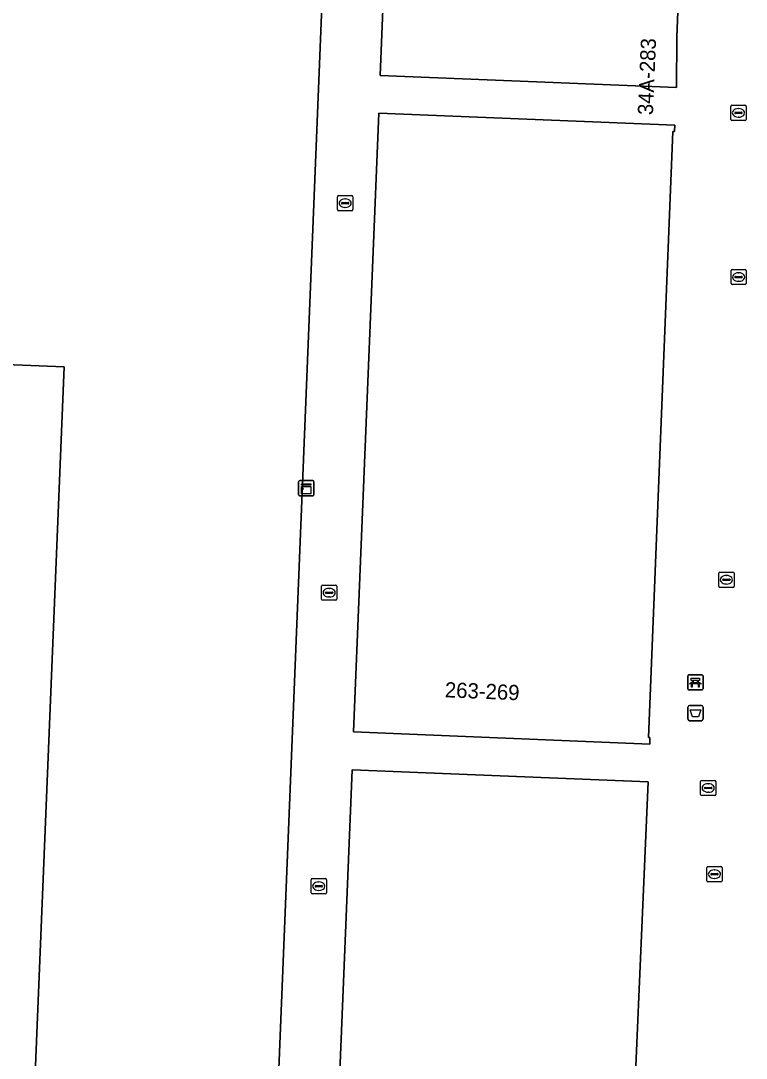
# Model space of a CAD drawing. Extents: x 160888 to 161385, y 386490 to 386908.
# Drawn here: x 161141.4 to 161189.1, y 386584.9 to 386653.1 of the extents above; entities that cross this region are included whole.
import ezdxf

# ---------------------------------------------------------------- set-up
doc = ezdxf.new("R2010")
doc.units = 0
for name, color, linetype in [('IMGEO_Afvalbak', 7, 'Continuous'), ('IMGEO_Bank', 7, 'Continuous'), ('IMGEO_Kast', 7, 'Continuous'), ('IMGEO_Kolk', 7, 'Continuous'), ('IMGEO_Pand', 7, 'Continuous'), ('IMGEO_Pand_nummerreeks', 7, 'Continuous'), ('IMGEO_Rioolput', 7, 'Continuous'), ('IMGEO_Voetgangersgebied_open', 7, 'Continuous')]:
    doc.layers.add(name, color=color, linetype=linetype)

msp = doc.modelspace()

# ---------------------------------------------------------------- linework, layer by layer
at = {"layer": 'IMGEO_Afvalbak'}
for p, q in [((161185.269, 386607.204), (161185.269, 386608.004)), ((161185.269, 386608.004), (161185.269, 386607.204)), ((161185.369, 386608.104), (161186.159, 386608.104)), ((161186.159, 386608.104), (161185.369, 386608.104)), ((161186.259, 386608.004), (161186.259, 386607.204)), ((161186.259, 386607.204), (161186.259, 386608.004)), ((161186.159, 386607.104), (161185.369, 386607.104)), ((161185.369, 386607.104), (161186.159, 386607.104))]:
    msp.add_line(p, q, dxfattribs=at)
msp.add_lwpolyline([(161185.412, 386607.818), (161186.116, 386607.818), (161185.967, 386607.348), (161185.561, 386607.348), (161185.412, 386607.818)], dxfattribs=at)
for centre, start, end in [((161185.369, 386608.004), 90, 180), ((161185.369, 386608.004), 90, 180), ((161186.159, 386608.004), 0, 90), ((161186.159, 386608.004), 360, 90), ((161185.369, 386607.204), 180, 270), ((161185.369, 386607.204), 180, 270), ((161186.159, 386607.204), 270, 0), ((161186.159, 386607.204), 270, 0)]:
    msp.add_arc(centre, 0.1, start, end, dxfattribs=at)
at = {"layer": 'IMGEO_Bank'}
for p, q in [((161185.256, 386609.198), (161185.256, 386610.039)), ((161185.256, 386610.039), (161185.256, 386609.198)), ((161185.331, 386610.123), (161186.172, 386610.123)), ((161186.172, 386610.123), (161185.331, 386610.123)), ((161186.256, 386610.048), (161186.256, 386609.207)), ((161186.256, 386609.207), (161186.256, 386610.048)), ((161185.953, 386609.521), (161185.56, 386609.521)), ((161185.565, 386609.629), (161185.565, 386609.735)), ((161185.609, 386609.735), (161185.609, 386609.629)), ((161185.897, 386609.741), (161185.615, 386609.741)), ((161185.615, 386609.623), (161185.897, 386609.623)), ((161185.903, 386609.629), (161185.903, 386609.735)), ((161185.947, 386609.735), (161185.947, 386609.629)), ((161186.181, 386609.123), (161185.34, 386609.123)), ((161185.34, 386609.123), (161186.181, 386609.123))]:
    msp.add_line(p, q, dxfattribs=at)
for points in [[(161185.559, 386609.741), (161185.473, 386609.741), (161185.473, 386609.902), (161186.036, 386609.902), (161186.036, 386609.741), (161185.953, 386609.741)], [(161185.503, 386609.521), (161185.361, 386609.521), (161185.473, 386609.623), (161185.559, 386609.623)], [(161185.553, 386609.514), (161185.553, 386609.307), (161185.51, 386609.307), (161185.51, 386609.514)], [(161185.953, 386609.623), (161186.036, 386609.623), (161186.148, 386609.521), (161186.009, 386609.521)], [(161186.003, 386609.514), (161186.003, 386609.307), (161185.959, 386609.307), (161185.959, 386609.514)]]:
    msp.add_lwpolyline(points, dxfattribs=at)
for centre, radius, start, end in [((161185.334, 386610.045), 0.0779, 92.4484, 184.28452), ((161185.334, 386610.045), 0.0779, 92.4484, 184.28452), ((161186.178, 386610.045), 0.0779, 2.4484, 94.28452), ((161186.178, 386610.045), 0.0779, 2.4484, 94.28452), ((161185.334, 386609.201), 0.0779, 182.4484, 274.28452), ((161185.334, 386609.201), 0.0779, 182.4484, 274.28452), ((161185.503, 386609.514), 0.00671, 2.89567, 87.10433), ((161185.56, 386609.514), 0.00671, 92.89567, 177.10433), ((161185.558, 386609.734), 0.00671, 2.89567, 87.10433), ((161185.558, 386609.63), 0.00671, 272.89567, 357.10433), ((161185.615, 386609.734), 0.00671, 92.89567, 177.10433), ((161185.615, 386609.63), 0.00671, 182.89567, 267.10433), ((161185.897, 386609.734), 0.00671, 2.89567, 87.10433), ((161185.897, 386609.63), 0.00671, 272.89567, 357.10433), ((161185.954, 386609.734), 0.00671, 92.89567, 177.10433), ((161185.954, 386609.63), 0.00671, 182.89567, 267.10433), ((161185.952, 386609.514), 0.00671, 2.89567, 87.10433), ((161186.009, 386609.514), 0.00671, 92.89567, 177.10433), ((161186.178, 386609.201), 0.0779, 272.4484, 4.28452), ((161186.178, 386609.201), 0.0779, 272.4484, 4.28452)]:
    msp.add_arc(centre, radius, start, end, dxfattribs=at)
at = {"layer": 'IMGEO_Kast'}
for p, q in [((161159.738, 386622.889), (161160.579, 386622.889)), ((161160.579, 386622.889), (161159.738, 386622.889)), ((161159.663, 386621.964), (161159.663, 386622.805)), ((161159.663, 386622.805), (161159.663, 386621.964)), ((161160.663, 386622.814), (161160.663, 386621.973)), ((161160.663, 386621.973), (161160.663, 386622.814)), ((161160.588, 386621.889), (161159.747, 386621.889)), ((161159.747, 386621.889), (161160.588, 386621.889))]:
    msp.add_line(p, q, dxfattribs=at)
for points in [[(161159.858, 386622.679), (161160.458, 386622.679), (161160.458, 386622.594), (161159.858, 386622.594), (161159.858, 386622.679)], [(161159.858, 386622.504), (161160.458, 386622.504), (161160.458, 386622.015), (161159.858, 386622.015), (161159.858, 386622.504)]]:
    msp.add_lwpolyline(points, dxfattribs=at)
msp.add_circle((161159.942, 386622.353), 0.0377, dxfattribs=at)
for centre, start, end in [((161159.741, 386622.811), 92.4484, 184.28452), ((161159.741, 386622.811), 92.4484, 184.28452), ((161160.585, 386622.811), 2.4484, 94.28452), ((161160.585, 386622.811), 2.4484, 94.28452), ((161159.741, 386621.967), 182.4484, 274.28452), ((161159.741, 386621.967), 182.4484, 274.28452), ((161160.585, 386621.967), 272.4484, 4.28452), ((161160.585, 386621.967), 272.4484, 4.28452)]:
    msp.add_arc(centre, 0.0779, start, end, dxfattribs=at)
at = {"layer": 'IMGEO_Kolk'}
for p, q in [((161162.226, 386640.703), (161162.226, 386641.555)), ((161162.301, 386641.629), (161163.153, 386641.629)), ((161162.714, 386641.409), (161162.739, 386641.409)), ((161163.227, 386641.555), (161163.227, 386640.703)), ((161163.153, 386640.629), (161162.301, 386640.629)), ((161162.485, 386641.123), (161162.485, 386641.135)), ((161162.923, 386641.086), (161162.525, 386641.086)), ((161162.528, 386641.172), (161162.926, 386641.172)), ((161162.737, 386640.849), (161162.712, 386640.849)), ((161162.969, 386641.135), (161162.969, 386641.123)), ((161188.098, 386635.846), (161188.098, 386636.698)), ((161188.173, 386636.772), (161189.025, 386636.772)), ((161188.586, 386636.552), (161188.611, 386636.552)), ((161189.099, 386636.698), (161189.099, 386635.846)), ((161188.357, 386636.266), (161188.357, 386636.278)), ((161188.795, 386636.229), (161188.397, 386636.229)), ((161188.4, 386636.315), (161188.798, 386636.315)), ((161188.609, 386635.992), (161188.584, 386635.992)), ((161188.841, 386636.278), (161188.841, 386636.266)), ((161189.025, 386635.772), (161188.173, 386635.772)), ((161187.293, 386615.945), (161187.293, 386616.797)), ((161187.368, 386616.871), (161188.22, 386616.871)), ((161188.294, 386616.797), (161188.294, 386615.945)), ((161161.252, 386616.02), (161162.104, 386616.02)), ((161187.552, 386616.365), (161187.552, 386616.377)), ((161187.99, 386616.328), (161187.592, 386616.328)), ((161187.595, 386616.414), (161187.993, 386616.414)), ((161187.804, 386616.091), (161187.779, 386616.091)), ((161187.781, 386616.651), (161187.806, 386616.651)), ((161188.036, 386616.377), (161188.036, 386616.365)), ((161161.177, 386615.094), (161161.177, 386615.946)), ((161161.436, 386615.514), (161161.436, 386615.526)), ((161161.874, 386615.477), (161161.476, 386615.477)), ((161161.479, 386615.563), (161161.877, 386615.563)), ((161161.665, 386615.8), (161161.69, 386615.8)), ((161161.92, 386615.526), (161161.92, 386615.514)), ((161162.178, 386615.946), (161162.178, 386615.094)), ((161188.22, 386615.871), (161187.368, 386615.871)), ((161162.104, 386615.02), (161161.252, 386615.02)), ((161161.688, 386615.24), (161161.663, 386615.24)), ((161186.506, 386596.586), (161186.506, 386597.438)), ((161186.581, 386597.512), (161187.433, 386597.512)), ((161186.765, 386597.006), (161186.765, 386597.018)), ((161187.203, 386596.969), (161186.805, 386596.969)), ((161186.808, 386597.055), (161187.206, 386597.055)), ((161186.994, 386597.292), (161187.019, 386597.292)), ((161187.249, 386597.018), (161187.249, 386597.006)), ((161187.507, 386597.438), (161187.507, 386596.586)), ((161160.489, 386595.797), (161160.489, 386596.649)), ((161160.564, 386596.723), (161161.416, 386596.723)), ((161160.748, 386596.217), (161160.748, 386596.229)), ((161160.791, 386596.266), (161161.189, 386596.266)), ((161160.977, 386596.503), (161161.002, 386596.503)), ((161161.232, 386596.229), (161161.232, 386596.217)), ((161161.49, 386596.649), (161161.49, 386595.797)), ((161187.433, 386596.512), (161186.581, 386596.512)), ((161187.017, 386596.732), (161186.992, 386596.732)), ((161161.416, 386595.723), (161160.564, 386595.723)), ((161161.186, 386596.18), (161160.788, 386596.18)), ((161161, 386595.943), (161160.975, 386595.943))]:
    msp.add_line(p, q, dxfattribs=at)
for points in [[(161162.226, 386640.703), (161162.226, 386641.555)], [(161162.301, 386641.629), (161163.153, 386641.629)], [(161163.227, 386641.555), (161163.227, 386640.703)], [(161163.153, 386640.629), (161162.301, 386640.629)], [(161188.098, 386635.846), (161188.098, 386636.698)], [(161188.173, 386636.772), (161189.025, 386636.772)], [(161189.099, 386636.698), (161189.099, 386635.846)], [(161189.025, 386635.772), (161188.173, 386635.772)], [(161187.293, 386615.945), (161187.293, 386616.797)], [(161187.368, 386616.871), (161188.22, 386616.871)], [(161188.294, 386616.797), (161188.294, 386615.945)], [(161161.252, 386616.02), (161162.104, 386616.02)], [(161161.177, 386615.094), (161161.177, 386615.946)], [(161162.178, 386615.946), (161162.178, 386615.094)], [(161188.22, 386615.871), (161187.368, 386615.871)], [(161162.104, 386615.02), (161161.252, 386615.02)], [(161186.506, 386596.586), (161186.506, 386597.438)], [(161186.581, 386597.512), (161187.433, 386597.512)], [(161187.507, 386597.438), (161187.507, 386596.586)], [(161160.489, 386595.797), (161160.489, 386596.649)], [(161160.564, 386596.723), (161161.416, 386596.723)], [(161161.49, 386596.649), (161161.49, 386595.797)], [(161187.433, 386596.512), (161186.581, 386596.512)], [(161161.416, 386595.723), (161160.564, 386595.723)]]:
    msp.add_lwpolyline(points, dxfattribs=at)
for centre, radius, start, end in [((161162.303, 386641.553), 0.0765, 91.55205, 178.44795), ((161162.303, 386641.553), 0.0765, 91.55205, 178.44795), ((161163.151, 386641.553), 0.0765, 1.55205, 88.44795), ((161163.151, 386641.553), 0.0765, 1.55205, 88.44795), ((161162.303, 386640.705), 0.0765, 181.55205, 268.44795), ((161162.303, 386640.705), 0.0765, 181.55205, 268.44795), ((161162.525, 386641.132), 0.0403, 85.87752, 175.75265), ((161162.522, 386641.122), 0.0366, 178.93798, 274.71019), ((161162.926, 386641.129), 0.043, 264.86636, 352.45326), ((161162.93, 386641.134), 0.0386, 1.73085, 96.63898), ((161163.151, 386640.705), 0.0765, 271.55205, 358.44795), ((161163.151, 386640.705), 0.0765, 271.55205, 358.44795), ((161188.175, 386636.696), 0.0765, 91.55205, 178.44795), ((161188.175, 386636.696), 0.0765, 91.55205, 178.44795), ((161189.023, 386636.696), 0.0765, 1.55205, 88.44795), ((161189.023, 386636.696), 0.0765, 1.55205, 88.44795), ((161188.175, 386635.848), 0.0765, 181.55205, 268.44795), ((161188.175, 386635.848), 0.0765, 181.55205, 268.44795), ((161188.397, 386636.275), 0.0403, 85.87752, 175.75265), ((161188.394, 386636.265), 0.0366, 178.93798, 274.71019), ((161188.798, 386636.272), 0.043, 264.86636, 352.45326), ((161188.802, 386636.277), 0.0386, 1.73085, 96.63898), ((161189.023, 386635.848), 0.0765, 271.55205, 358.44795), ((161189.023, 386635.848), 0.0765, 271.55205, 358.44795), ((161187.37, 386616.795), 0.0765, 91.55205, 178.44795), ((161187.37, 386616.795), 0.0765, 91.55205, 178.44795), ((161188.218, 386616.795), 0.0765, 1.55205, 88.44795), ((161188.218, 386616.795), 0.0765, 1.55205, 88.44795), ((161161.254, 386615.944), 0.0765, 91.55205, 178.44795), ((161161.254, 386615.944), 0.0765, 91.55205, 178.44795), ((161162.102, 386615.944), 0.0765, 1.55205, 88.44795), ((161162.102, 386615.944), 0.0765, 1.55205, 88.44795), ((161187.592, 386616.374), 0.0403, 85.87752, 175.75265), ((161187.589, 386616.364), 0.0366, 178.93798, 274.71019), ((161187.993, 386616.371), 0.043, 264.86636, 352.45326), ((161187.997, 386616.376), 0.0386, 1.73085, 96.63898), ((161161.476, 386615.523), 0.0403, 85.87752, 175.75265), ((161161.473, 386615.513), 0.0366, 178.93798, 274.71019), ((161161.877, 386615.52), 0.043, 264.86636, 352.45326), ((161161.881, 386615.525), 0.0386, 1.73085, 96.63898), ((161187.37, 386615.947), 0.0765, 181.55205, 268.44795), ((161187.37, 386615.947), 0.0765, 181.55205, 268.44795), ((161188.218, 386615.947), 0.0765, 271.55205, 358.44795), ((161188.218, 386615.947), 0.0765, 271.55205, 358.44795), ((161161.254, 386615.096), 0.0765, 181.55205, 268.44795), ((161161.254, 386615.096), 0.0765, 181.55205, 268.44795), ((161162.102, 386615.096), 0.0765, 271.55205, 358.44795), ((161162.102, 386615.096), 0.0765, 271.55205, 358.44795), ((161186.583, 386597.436), 0.0765, 91.55205, 178.44795), ((161186.583, 386597.436), 0.0765, 91.55205, 178.44795), ((161186.805, 386597.015), 0.0403, 85.87752, 175.75265), ((161186.802, 386597.005), 0.0366, 178.93798, 274.71019), ((161187.206, 386597.012), 0.043, 264.86636, 352.45326), ((161187.21, 386597.017), 0.0386, 1.73085, 96.63898), ((161187.431, 386597.436), 0.0765, 1.55205, 88.44795), ((161187.431, 386597.436), 0.0765, 1.55205, 88.44795), ((161160.566, 386596.647), 0.0765, 91.55205, 178.44795), ((161160.566, 386596.647), 0.0765, 91.55205, 178.44795), ((161160.788, 386596.226), 0.0403, 85.87752, 175.75265), ((161161.193, 386596.228), 0.0386, 1.73085, 96.63898), ((161161.414, 386596.647), 0.0765, 1.55205, 88.44795), ((161161.414, 386596.647), 0.0765, 1.55205, 88.44795), ((161186.583, 386596.588), 0.0765, 181.55205, 268.44795), ((161186.583, 386596.588), 0.0765, 181.55205, 268.44795), ((161187.431, 386596.588), 0.0765, 271.55205, 358.44795), ((161187.431, 386596.588), 0.0765, 271.55205, 358.44795), ((161160.566, 386595.799), 0.0765, 181.55205, 268.44795), ((161160.566, 386595.799), 0.0765, 181.55205, 268.44795), ((161160.785, 386596.216), 0.0366, 178.93798, 274.71019), ((161161.189, 386596.223), 0.043, 264.86636, 352.45326), ((161161.414, 386595.799), 0.0765, 271.55205, 358.44795), ((161161.414, 386595.799), 0.0765, 271.55205, 358.44795)]:
    msp.add_arc(centre, radius, start, end, dxfattribs=at)
for centre, major_axis, ratio, start_param, end_param in [((161162.713, 386641.129), (-0.387, 0.002), 0.722429, 4.712389, 7.853982), ((161162.738, 386641.129), (-0.39, 0.002), 0.717154, 1.570796, 4.712389), ((161188.585, 386636.272), (-0.387, 0.002), 0.722429, 4.712389, 7.853982), ((161188.61, 386636.272), (-0.39, 0.002), 0.717154, 1.570796, 4.712389), ((161187.78, 386616.371), (-0.387, 0.002), 0.722429, 4.712389, 7.853982), ((161187.805, 386616.371), (-0.39, 0.002), 0.717154, 1.570796, 4.712389), ((161161.664, 386615.52), (-0.387, 0.002), 0.722429, 4.712389, 7.853982), ((161161.689, 386615.52), (-0.39, 0.002), 0.717154, 1.570796, 4.712389), ((161186.993, 386597.012), (-0.387, 0.002), 0.722429, 4.712389, 7.853982), ((161187.018, 386597.012), (-0.39, 0.002), 0.717154, 1.570796, 4.712389), ((161160.976, 386596.223), (-0.387, 0.002), 0.722429, 4.712389, 7.853982), ((161161.001, 386596.223), (-0.39, 0.002), 0.717154, 1.570796, 4.712389)]:
    msp.add_ellipse(centre, major_axis=major_axis, ratio=ratio, start_param=start_param, end_param=end_param, dxfattribs=at)
at = {"layer": 'IMGEO_Pand'}
for points in [[(161158.269, 386582.057), (161161.964, 386673.038), (161165.981, 386672.875), (161165.034, 386649.524), (161184.503, 386648.738), (161184.541, 386652.073), (161186.449, 386699.801), (161186.412, 386700.854), (161186.212, 386702.035), (161185.839, 386703.176), (161185.308, 386704.253), (161184.602, 386705.296), (161183.781, 386706.174)], [(161136.014, 386630.69), (161144.239, 386630.361), (161141.97, 386574.785)], [(161181.347, 386573.278), (161182.646, 386603.083), (161163.18, 386603.875), (161162.285, 386581.893)]]:
    msp.add_lwpolyline(points, dxfattribs=at)
msp.add_lwpolyline([(161163.276, 386606.37), (161182.75, 386605.57), (161182.762, 386605.989), (161182.662, 386605.991), (161184.281, 386645.835), (161184.381, 386645.831), (161184.399, 386646.246), (161164.933, 386647.036)], close=True, dxfattribs=at)
at = {"layer": 'IMGEO_Rioolput'}
for p, q in [((161188.084, 386646.637), (161188.084, 386647.489)), ((161188.159, 386647.563), (161189.011, 386647.563)), ((161189.085, 386647.489), (161189.085, 386646.637)), ((161188.343, 386647.057), (161188.343, 386647.069)), ((161188.781, 386647.02), (161188.383, 386647.02)), ((161188.386, 386647.106), (161188.784, 386647.106)), ((161188.595, 386646.783), (161188.57, 386646.783)), ((161188.572, 386647.343), (161188.597, 386647.343)), ((161188.827, 386647.069), (161188.827, 386647.057)), ((161189.011, 386646.563), (161188.159, 386646.563)), ((161186.098, 386602.254), (161186.098, 386603.106)), ((161186.173, 386603.18), (161187.025, 386603.18)), ((161187.099, 386603.106), (161187.099, 386602.254)), ((161186.357, 386602.674), (161186.357, 386602.686)), ((161186.795, 386602.637), (161186.397, 386602.637)), ((161186.4, 386602.723), (161186.798, 386602.723)), ((161186.609, 386602.4), (161186.584, 386602.4)), ((161186.586, 386602.96), (161186.611, 386602.96)), ((161186.841, 386602.686), (161186.841, 386602.674)), ((161187.025, 386602.18), (161186.173, 386602.18))]:
    msp.add_line(p, q, dxfattribs=at)
for points in [[(161188.084, 386646.637), (161188.084, 386647.489)], [(161188.159, 386647.563), (161189.011, 386647.563)], [(161189.085, 386647.489), (161189.085, 386646.637)], [(161189.011, 386646.563), (161188.159, 386646.563)], [(161186.098, 386602.254), (161186.098, 386603.106)], [(161186.173, 386603.18), (161187.025, 386603.18)], [(161187.099, 386603.106), (161187.099, 386602.254)], [(161187.025, 386602.18), (161186.173, 386602.18)]]:
    msp.add_lwpolyline(points, dxfattribs=at)
for centre, radius, start, end in [((161188.161, 386647.487), 0.0765, 91.55205, 178.44795), ((161188.161, 386647.487), 0.0765, 91.55205, 178.44795), ((161189.009, 386647.487), 0.0765, 1.55205, 88.44795), ((161189.009, 386647.487), 0.0765, 1.55205, 88.44795), ((161188.383, 386647.066), 0.0403, 85.87752, 175.75265), ((161188.38, 386647.056), 0.0366, 178.93798, 274.71019), ((161188.784, 386647.063), 0.043, 264.86636, 352.45326), ((161188.788, 386647.068), 0.0386, 1.73085, 96.63898), ((161188.161, 386646.639), 0.0765, 181.55205, 268.44795), ((161188.161, 386646.639), 0.0765, 181.55205, 268.44795), ((161189.009, 386646.639), 0.0765, 271.55205, 358.44795), ((161189.009, 386646.639), 0.0765, 271.55205, 358.44795), ((161186.175, 386603.104), 0.0765, 91.55205, 178.44795), ((161186.175, 386603.104), 0.0765, 91.55205, 178.44795), ((161187.023, 386603.104), 0.0765, 1.55205, 88.44795), ((161187.023, 386603.104), 0.0765, 1.55205, 88.44795), ((161186.397, 386602.683), 0.0403, 85.87752, 175.75265), ((161186.394, 386602.673), 0.0366, 178.93798, 274.71019), ((161186.798, 386602.68), 0.043, 264.86636, 352.45326), ((161186.802, 386602.685), 0.0386, 1.73085, 96.63898), ((161186.175, 386602.256), 0.0765, 181.55205, 268.44795), ((161186.175, 386602.256), 0.0765, 181.55205, 268.44795), ((161187.023, 386602.256), 0.0765, 271.55205, 358.44795), ((161187.023, 386602.256), 0.0765, 271.55205, 358.44795)]:
    msp.add_arc(centre, radius, start, end, dxfattribs=at)
for centre, major_axis, ratio, start_param, end_param in [((161188.571, 386647.063), (-0.387, 0.002), 0.722429, 4.712389, 7.853982), ((161188.596, 386647.063), (-0.39, 0.002), 0.717154, 1.570796, 4.712389), ((161186.585, 386602.68), (-0.387, 0.002), 0.722429, 4.712389, 7.853982), ((161186.61, 386602.68), (-0.39, 0.002), 0.717154, 1.570796, 4.712389)]:
    msp.add_ellipse(centre, major_axis=major_axis, ratio=ratio, start_param=start_param, end_param=end_param, dxfattribs=at)
at = {"layer": 'IMGEO_Voetgangersgebied_open'}
for points in [[(161183.781, 386706.174), (161184.602, 386705.296), (161185.308, 386704.253), (161185.839, 386703.176), (161186.212, 386702.035), (161186.412, 386700.854), (161186.449, 386699.801), (161184.541, 386652.073), (161184.503, 386648.738), (161165.034, 386649.524), (161165.981, 386672.875), (161161.964, 386673.038), (161158.269, 386582.057)], [(161139.877, 386568.704), (161143.412, 386571.685), (161142.623, 386572.549), (161142.127, 386573.608), (161141.97, 386574.785), (161144.239, 386630.361), (161136.014, 386630.69)], [(161162.285, 386581.893), (161163.18, 386603.875), (161182.646, 386603.083), (161181.347, 386573.278)]]:
    msp.add_lwpolyline(points, dxfattribs=at)
msp.add_lwpolyline([(161182.662, 386605.991), (161182.762, 386605.989), (161182.75, 386605.57), (161163.276, 386606.37), (161164.933, 386647.036), (161184.399, 386646.246), (161184.381, 386645.831), (161184.281, 386645.835)], close=True, dxfattribs=at)

# ---------------------------------------------------------------- texts
at = {"layer": 'IMGEO_Pand_nummerreeks'}
for s, rotation, p in [('34A-283', 87.55034, (161182.96, 386646.902)), ('263-269', 357.64759, (161169.267, 386608.646))]:
    msp.add_text(s, height=1, rotation=rotation, dxfattribs=at).set_placement(p)

doc.saveas('drawing.dxf')
